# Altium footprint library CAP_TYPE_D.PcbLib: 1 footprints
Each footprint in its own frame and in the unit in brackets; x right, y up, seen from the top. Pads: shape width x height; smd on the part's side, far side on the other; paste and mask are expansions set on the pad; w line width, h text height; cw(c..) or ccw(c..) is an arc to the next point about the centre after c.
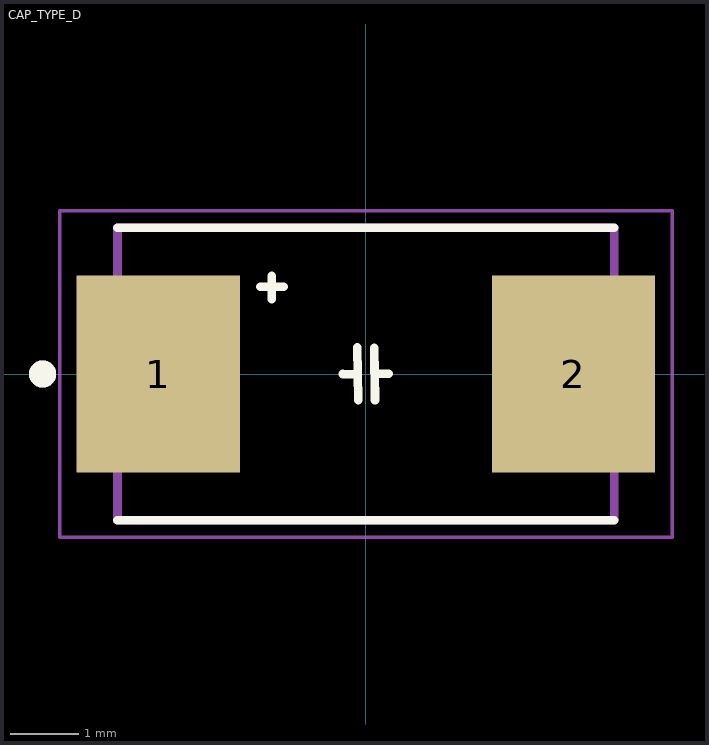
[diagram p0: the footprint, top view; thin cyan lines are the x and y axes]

## CAP_TYPE_D [mm]
pads (2):
  rect 2.4x2.9 smd: 1(-3.05,0) 2(3.05,0)
Top Overlay:
  circle w0.2: c-4.75,0 r0.1
  lines w0.127: -3.65,-2.15 3.65,-2.15 ; -3.65,2.15 3.65,2.15 ; -1.551,1.28 -1.208,1.279 ; -1.385,1.101 -1.384,1.444 ; -0.342,-0.001 -0.12,-0.001 ; -0.126,0.389 -0.115,-0.381 ; 0.121,0.385 0.133,-0.385 ; 0.153,0.003 0.333,0.003
Mechanical 13:
  circle w0.2: c-4.75,0 r0.1
  lines w0.127: -3.65,-2.15 -3.65,2.15 3.65,2.15 3.65,-2.15 -3.65,-2.15
Mechanical 15:
  lines w0.05: -4.5,-2.4 -4.5,2.4 4.5,2.4 4.5,-2.4 -4.5,-2.4
3D body "CAP_TYPE_D.STEP": height 3.1, standoff 0, extent -3.65,-2.15 3.65,2.15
